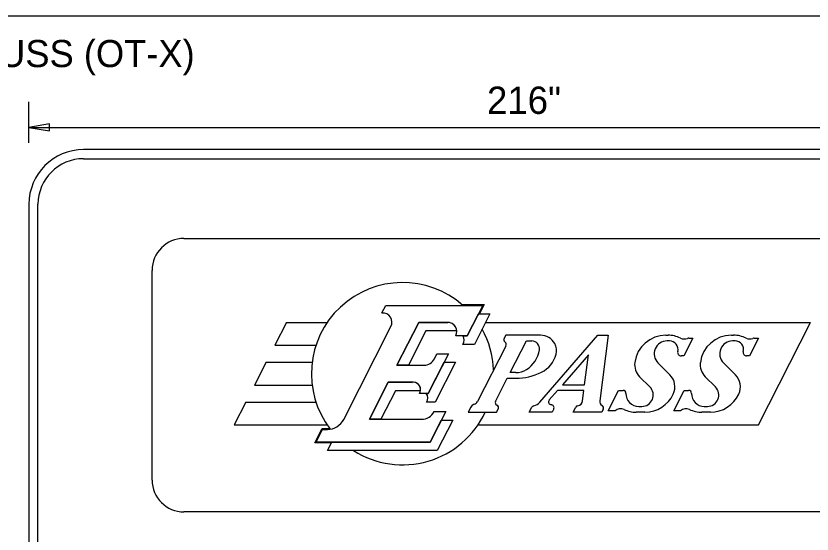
# Model space of a CAD drawing. Extents: x 10268312 to 10268706, y 2142548 to 2142786.
# Drawn here: x 10268433.11 to 10268453.64, y 2142674.17 to 2142687.53 of the extents above; entities that cross this region are included whole.
import ezdxf

# ---------------------------------------------------------------- set-up
doc = ezdxf.new("R2010")
doc.units = 0
for name, color, linetype in [('GSBWFill', 7, 'Continuous'), ('GSDims', 7, 'Continuous'), ('SignPanel', 7, 'Continuous'), ('SumBoxLines_dp', 7, 'Continuous')]:
    doc.layers.add(name, color=color, linetype=linetype)

msp = doc.modelspace()

# ---------------------------------------------------------------- linework, layer by layer
at = {"layer": 'GSBWFill'}
for p, q in [((10268433.445, 2142684.26), (10268433.445, 2142685.318)), ((10268457.434, 2142684.084), (10268434.856, 2142684.084)), ((10268434.856, 2142683.849), (10268457.434, 2142683.849))]:
    msp.add_line(p, q, dxfattribs=at)
msp.add_lwpolyline([(10268433.445, 2142682.673), (10268433.445, 2142666.857), (10268433.68, 2142666.857), (10268433.68, 2142682.673)], dxfattribs=at)
for radius in [1.411, 1.176]:
    msp.add_arc((10268434.856, 2142682.673), radius, 90, 180, dxfattribs=at)
at = {"layer": 'GSDims'}
msp.add_line((10268433.445, 2142684.657), (10268458.846, 2142684.657), dxfattribs=at)
msp.add_lwpolyline([(10268433.445, 2142684.657), (10268433.974, 2142684.569), (10268433.974, 2142684.745)], close=True, dxfattribs=at)
at = {"layer": 'SignPanel'}
for p, q in [((10268437.445, 2142681.791), (10268454.845, 2142681.791)), ((10268436.622, 2142675.56), (10268436.622, 2142680.968)), ((10268442.551, 2142679.869), (10268442.651, 2142680.066)), ((10268442.651, 2142680.066), (10268445.15, 2142680.066)), ((10268444.612, 2142680.088), (10268445.185, 2142680.088)), ((10268445.15, 2142680.066), (10268444.749, 2142679.281)), ((10268445.185, 2142680.088), (10268445.062, 2142679.846)), ((10268444.749, 2142679.28), (10268445.037, 2142679.846)), ((10268445.334, 2142679.846), (10268444.934, 2142679.06)), ((10268445.037, 2142679.846), (10268445.334, 2142679.846)), ((10268440.085, 2142679.625), (10268439.785, 2142679.038)), ((10268440.085, 2142679.625), (10268441.138, 2142679.625)), ((10268443.498, 2142679.625), (10268442.936, 2142678.523)), ((10268442.936, 2142678.523), (10268443.498, 2142679.625)), ((10268444.247, 2142679.625), (10268443.498, 2142679.625)), ((10268443.498, 2142679.625), (10268444.247, 2142679.625)), ((10268445.221, 2142679.625), (10268453.605, 2142679.625)), ((10268452.257, 2142676.98), (10268453.605, 2142679.625)), ((10268441.563, 2142677.123), (10268442.783, 2142679.517)), ((10268443.682, 2142679.405), (10268443.233, 2142678.523)), ((10268444.482, 2142679.405), (10268443.682, 2142679.405)), ((10268444.749, 2142679.281), (10268444.455, 2142679.281)), ((10268444.639, 2142679.28), (10268444.749, 2142679.28)), ((10268445.743, 2142679.295), (10268445.702, 2142679.216)), ((10268446.642, 2142679.295), (10268445.743, 2142679.295)), ((10268446.62, 2142677.569), (10268448.121, 2142679.295)), ((10268448.121, 2142679.295), (10268448.385, 2142679.295)), ((10268448.385, 2142679.295), (10268448.165, 2142677.604)), ((10268449.871, 2142679.295), (10268449.927, 2142679.295)), ((10268450.571, 2142679.221), (10268450.337, 2142678.763)), ((10268450.461, 2142679.221), (10268450.571, 2142679.221)), ((10268451.562, 2142679.295), (10268451.617, 2142679.295)), ((10268452.261, 2142679.221), (10268452.027, 2142678.763)), ((10268452.15, 2142679.221), (10268452.261, 2142679.221)), ((10268439.785, 2142679.038), (10268440.849, 2142679.038)), ((10268444.934, 2142679.06), (10268444.64, 2142679.06)), ((10268445.745, 2142679.017), (10268445.017, 2142677.589)), ((10268445.858, 2142678.332), (10268446.274, 2142679.148)), ((10268445.858, 2142678.332), (10268446.274, 2142679.148)), ((10268446.274, 2142679.148), (10268446.415, 2142679.148)), ((10268446.274, 2142679.148), (10268446.415, 2142679.148)), ((10268449.965, 2142679.148), (10268449.902, 2142679.148)), ((10268451.655, 2142679.148), (10268451.592, 2142679.148)), ((10268444.263, 2142678.817), (10268443.739, 2142677.788)), ((10268443.901, 2142678.684), (10268443.969, 2142678.817)), ((10268443.969, 2142678.817), (10268444.263, 2142678.817)), ((10268447.874, 2142678.788), (10268447.204, 2142678.016)), ((10268447.874, 2142678.788), (10268447.204, 2142678.016)), ((10268447.774, 2142678.016), (10268447.874, 2142678.788)), ((10268447.774, 2142678.016), (10268447.874, 2142678.788)), ((10268439.561, 2142678.597), (10268439.262, 2142678.009)), ((10268439.561, 2142678.597), (10268440.749, 2142678.597)), ((10268443.739, 2142677.788), (10268444.151, 2142678.597)), ((10268444.448, 2142678.597), (10268443.923, 2142677.568)), ((10268444.151, 2142678.597), (10268444.448, 2142678.597)), ((10268449.668, 2142678.583), (10268449.976, 2142678.275)), ((10268450.337, 2142678.763), (10268450.264, 2142678.763)), ((10268451.358, 2142678.583), (10268451.666, 2142678.275)), ((10268452.027, 2142678.763), (10268451.954, 2142678.763)), ((10268442.936, 2142678.523), (10268443.639, 2142678.523)), ((10268443.233, 2142678.523), (10268442.936, 2142678.523)), ((10268445.479, 2142677.589), (10268445.783, 2142678.185)), ((10268445.783, 2142678.185), (10268446.003, 2142678.185)), ((10268446.003, 2142678.332), (10268445.858, 2142678.332)), ((10268446.003, 2142678.332), (10268445.858, 2142678.332)), ((10268449.46, 2142677.96), (10268449.196, 2142678.224)), ((10268451.15, 2142677.96), (10268450.886, 2142678.224)), ((10268439.262, 2142678.009), (10268440.749, 2142678.009)), ((10268442.712, 2142678.082), (10268442.225, 2142677.127)), ((10268442.225, 2142677.127), (10268442.712, 2142678.082)), ((10268443.357, 2142678.082), (10268442.712, 2142678.082)), ((10268442.712, 2142678.082), (10268443.329, 2142678.08)), ((10268447.204, 2142678.016), (10268447.774, 2142678.016)), ((10268447.204, 2142678.016), (10268447.774, 2142678.016)), ((10268442.896, 2142677.861), (10268442.522, 2142677.127)), ((10268443.545, 2142677.859), (10268442.896, 2142677.861)), ((10268443.739, 2142677.788), (10268443.518, 2142677.788)), ((10268443.693, 2142677.788), (10268443.739, 2142677.788)), ((10268447.076, 2142677.869), (10268446.863, 2142677.625)), ((10268447.759, 2142677.869), (10268447.076, 2142677.869)), ((10268447.724, 2142677.604), (10268447.759, 2142677.869)), ((10268448.384, 2142677.348), (10268448.651, 2142677.871)), ((10268448.651, 2142677.871), (10268448.769, 2142677.871)), ((10268450.074, 2142677.348), (10268450.341, 2142677.871)), ((10268450.341, 2142677.871), (10268450.459, 2142677.871)), ((10268439.037, 2142677.568), (10268438.738, 2142676.98)), ((10268439.037, 2142677.568), (10268440.849, 2142677.568)), ((10268443.923, 2142677.568), (10268443.703, 2142677.568)), ((10268444.839, 2142677.44), (10268444.773, 2142677.311)), ((10268445.508, 2142677.311), (10268445.547, 2142677.389)), ((10268446.349, 2142677.311), (10268446.414, 2142677.437)), ((10268446.981, 2142677.396), (10268446.937, 2142677.311)), ((10268447.484, 2142677.311), (10268447.549, 2142677.438)), ((10268448.257, 2142677.387), (10268448.218, 2142677.311)), ((10268448.563, 2142677.348), (10268448.384, 2142677.348)), ((10268449.173, 2142677.458), (10268449.252, 2142677.458)), ((10268450.253, 2142677.348), (10268450.074, 2142677.348)), ((10268450.863, 2142677.458), (10268450.942, 2142677.458)), ((10268442.225, 2142677.127), (10268443.574, 2142677.127)), ((10268442.522, 2142677.127), (10268442.225, 2142677.127)), ((10268444.194, 2142677.325), (10268443.793, 2142676.539)), ((10268443.899, 2142677.325), (10268444.194, 2142677.325)), ((10268444.773, 2142677.311), (10268445.508, 2142677.311)), ((10268446.937, 2142677.311), (10268446.349, 2142677.311)), ((10268448.218, 2142677.311), (10268447.484, 2142677.311)), ((10268449.331, 2142677.311), (10268449.11, 2142677.311)), ((10268451.021, 2142677.311), (10268450.8, 2142677.311)), ((10268438.738, 2142676.98), (10268441.138, 2142676.98)), ((10268443.793, 2142676.539), (10268444.081, 2142677.105)), ((10268444.378, 2142677.105), (10268443.978, 2142676.319)), ((10268444.081, 2142677.105), (10268444.378, 2142677.105)), ((10268445.027, 2142676.98), (10268452.257, 2142676.98)), ((10268440.823, 2142676.52), (10268441.009, 2142676.886)), ((10268440.854, 2142676.539), (10268441.021, 2142676.867)), ((10268441.009, 2142676.886), (10268441.144, 2142676.886)), ((10268441.021, 2142676.867), (10268441.144, 2142676.867)), ((10268441.25, 2142676.52), (10268440.823, 2142676.52)), ((10268443.793, 2142676.539), (10268440.854, 2142676.539)), ((10268441.148, 2142676.319), (10268441.26, 2142676.539)), ((10268441.26, 2142676.539), (10268443.793, 2142676.539)), ((10268443.978, 2142676.319), (10268441.148, 2142676.319)), ((10268454.845, 2142674.737), (10268437.445, 2142674.737))]:
    msp.add_line(p, q, dxfattribs=at)
for centre, radius, start, end in [((10268437.445, 2142680.968), 0.823, 90, 180), ((10268443.082, 2142678.303), 2.351, 48.5904, 217.4727), ((10268442.567, 2142679.627), 0.242, 332.9998, 93.8045), ((10268444.247, 2142679.39), 0.235, 332.2089, 90), ((10268444.247, 2142679.39), 0.235, 3.5833, 90), ((10268443.082, 2142678.303), 2.351, 2.4236, 29.2771), ((10268444.431, 2142679.17), 0.235, 332.2089, 27.9127), ((10268445.768, 2142679.183), 0.0735, 152.9784, 231.1602), ((10268446.642, 2142678.876), 0.419, 29.4315, 90), ((10268449.871, 2142678.486), 0.808, 90, 172.3089), ((10268449.927, 2142678.56), 0.735, 64.0896, 90), ((10268450.345, 2142679.419), 0.22, 244.0896, 292.0347), ((10268450.46, 2142679.133), 0.0882, 90, 112.0347), ((10268451.562, 2142678.486), 0.808, 90, 172.3089), ((10268451.617, 2142678.56), 0.735, 64.0896, 90), ((10268452.035, 2142679.419), 0.22, 244.0896, 292.0347), ((10268452.15, 2142679.133), 0.0882, 90, 112.0347), ((10268445.666, 2142679.057), 0.0882, 333.0027, 51.1602), ((10268446.415, 2142678.949), 0.198, 351.076, 90), ((10268446.415, 2142678.949), 0.198, 351.076, 90), ((10268446.687, 2142678.901), 0.367, 344.7074, 29.4315), ((10268449.902, 2142678.817), 0.331, 90, 225), ((10268449.965, 2142678.927), 0.22, 345.6915, 90), ((10268451.592, 2142678.817), 0.331, 90, 225), ((10268451.655, 2142678.927), 0.22, 345.6915, 90), ((10268445.885, 2142679.033), 0.735, 302.4206, 351.076), ((10268445.885, 2142679.033), 0.735, 302.4206, 351.076), ((10268446.333, 2142678.998), 0.735, 296.6431, 344.7074), ((10268450.264, 2142678.851), 0.0882, 165.6915, 270), ((10268451.954, 2142678.851), 0.0882, 165.6915, 270), ((10268443.639, 2142678.817), 0.294, 270, 332.9883), ((10268449.507, 2142678.536), 0.441, 172.3089, 225), ((10268451.197, 2142678.536), 0.441, 172.3089, 225), ((10268446.003, 2142678.846), 0.514, 270, 302.4206), ((10268446.003, 2142678.846), 0.514, 270, 302.4206), ((10268446.003, 2142679.655), 1.47, 270, 296.6431), ((10268449.664, 2142677.963), 0.441, 334.95, 45), ((10268451.354, 2142677.963), 0.441, 334.95, 45), ((10268443.356, 2142677.891), 0.191, 350.3502, 98.3344), ((10268443.356, 2142677.891), 0.191, 327.421, 90), ((10268449.252, 2142677.752), 0.294, 270, 45), ((10268450.942, 2142677.752), 0.294, 270, 45), ((10268443.542, 2142677.671), 0.191, 327.421, 37.9799), ((10268448.769, 2142677.798), 0.0735, 358.6664, 90), ((10268449.173, 2142677.788), 0.331, 178.6665, 270), ((10268449.331, 2142678.119), 0.808, 270, 334.95), ((10268450.459, 2142677.798), 0.0735, 358.6664, 90), ((10268450.863, 2142677.788), 0.331, 178.6665, 270), ((10268451.021, 2142678.119), 0.808, 270, 334.95), ((10268444.886, 2142677.655), 0.147, 286.4317, 332.9959), ((10268445.544, 2142677.556), 0.0735, 152.9884, 244.7832), ((10268446.398, 2142677.761), 0.294, 282.7162, 318.9966), ((10268446.919, 2142677.576), 0.0735, 138.9824, 268.6869), ((10268447.579, 2142677.622), 0.147, 279.2397, 352.5632), ((10268448.282, 2142677.588), 0.118, 172.5884, 241.8673), ((10268444.97, 2142677.374), 0.147, 106.4317, 152.9742), ((10268445.482, 2142677.423), 0.0735, 333.0239, 64.7832), ((10268446.479, 2142677.403), 0.0735, 102.7162, 153.0239), ((10268446.915, 2142677.429), 0.0735, 332.9784, 88.6869), ((10268447.614, 2142677.405), 0.0735, 99.2397, 153.0239), ((10268448.192, 2142677.42), 0.0735, 332.9784, 61.8673), ((10268448.703, 2142677.197), 0.206, 64.3795, 133.1892), ((10268449.11, 2142678.045), 0.735, 244.3795, 270), ((10268450.393, 2142677.197), 0.206, 64.3795, 133.1892), ((10268450.8, 2142678.045), 0.735, 244.3795, 270), ((10268443.082, 2142678.303), 2.351, 237.5383, 335.047), ((10268443.573, 2142677.494), 0.367, 270, 332.5096), ((10268441.144, 2142677.337), 0.47, 270, 332.9991), ((10268441.144, 2142677.337), 0.451, 270, 277.5038), ((10268437.445, 2142675.56), 0.823, 180, 270)]:
    msp.add_arc(centre, radius, start, end, dxfattribs=at)
at = {"layer": 'SumBoxLines_dp'}
msp.add_line((10268418.73, 2142687.532), (10268470.98, 2142687.532), dxfattribs=at)

# ---------------------------------------------------------------- texts
at = {"layer": 'GSDims'}
for s, height, p in [('MOUNTING: OVERHEAD TRUSS (OT-X)', 0.7, (10268420.3, 2142686.211)), ('216"', 0.7056, (10268445.259, 2142685.004))]:
    msp.add_text(s, height=height, dxfattribs=at).set_placement(p)

doc.saveas('drawing.dxf')
